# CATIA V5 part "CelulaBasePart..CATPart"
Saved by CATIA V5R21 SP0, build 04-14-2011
Part number: CelulaBasePart.
Bounding box of the stored display mesh (mm): x 0 to 180, y 0 to 180, z 0 to 6
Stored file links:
  C:\Users\fisic\Desktop\labirinto catia\CelulaBasePart..CATPart
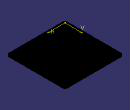
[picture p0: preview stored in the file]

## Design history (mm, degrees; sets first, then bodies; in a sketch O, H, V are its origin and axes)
Body1 (main body)
  Sketch1 on xy-plane, origin (0, 0, 0), H (1, 0, 0), V (0, 1, 0)
    construction line L1 (0, 200) -> (180, 200)
    construction line L2 (180, 200) -> (180, 180)
    construction line L3 (180, 180) -> (0, 180)
    construction line L4 (0, 180) -> (0, 200)
    point P3 (180, 180)
    distance P3 V = 180
    distance P3 H = 180
    horizontal: L1 H, L3 H
    vertical: L2 V, L4 V
  Sketch2 on xy-plane, origin (0, 0, 0), H (1, 0, 0), V (0, 1, 0)
    line L1 (0, 0) -> (180, 0)
    line L2 (180, 0) -> (180, 180)
    line L3 (180, 180) -> (0, 180)
    line L4 (0, 180) -> (0, 0)
    point P2 (180, 180)
    distance P2 V = 180
    distance P2 H = 180
    horizontal: L1 H, L3 H
    vertical: L2 V, L4 V
  Pad1: profile Sketch2, direction (0, 0, 1), length 6
  Sketch3 on end face of Pad1, origin (0, 0, 6), H (1, 0, 0), V (0, 1, 0)
    circle A1 centre (180, 0) radius 2.25
    point P1 (180, 0)
    circle A2 centre (0, 0) radius 2.25
    circle A3 centre (180, 180) radius 2.25
    circle A4 centre (0, 180) radius 2.25
    point P3 (0, 180)
    coincidence: P1 H, P3 V
  Pocket1: profile Sketch3, direction (0, 0, -1), length 6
